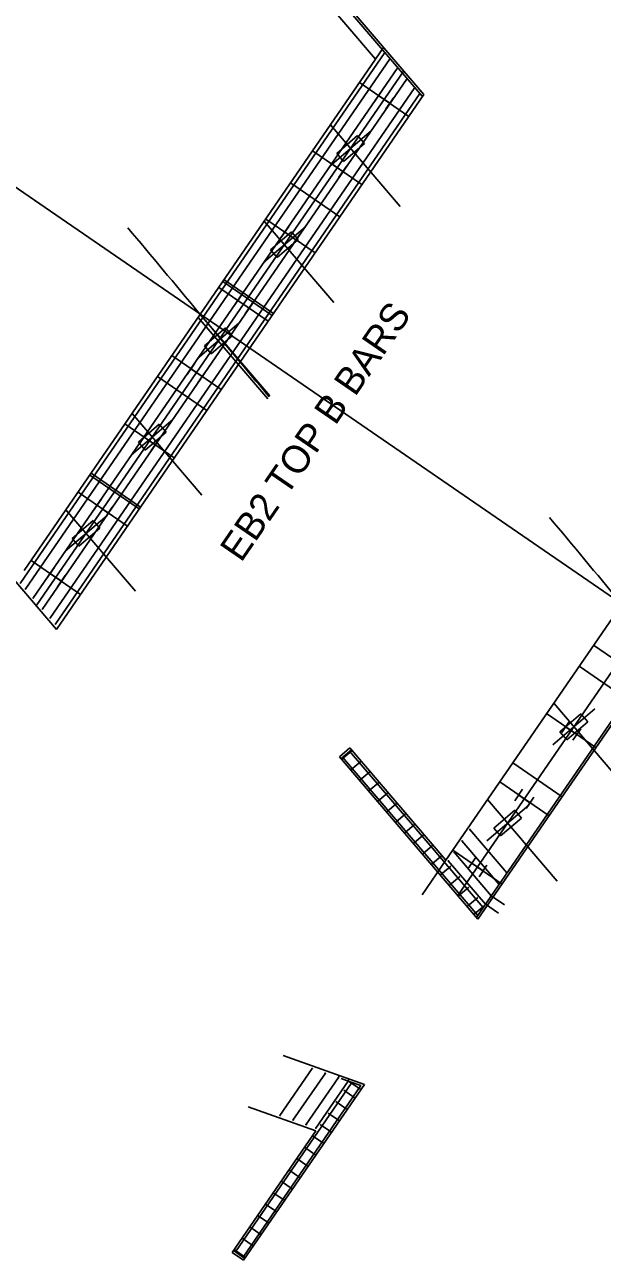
# Model space of a CAD drawing. Extents: x 2378999 to 2381348, y 331302 to 333122.
# Drawn here: x 2379481.1 to 2379522.9, y 331849.1 to 331938.5 of the extents above; entities that cross this region are included whole.
import ezdxf

# ---------------------------------------------------------------- set-up
doc = ezdxf.new("R2010")
doc.units = 0
for name, color, linetype in [('Arrowhead Terminators', 7, 'Continuous'), ('Arrowhead Terminators CELL', 7, 'Continuous'), ('Dimension Lines', 7, 'Continuous'), ('Dimension Lines CELL', 7, 'Continuous'), ('Mis Work Point CELL', 7, 'Continuous'), ('P_SMU_Bent_Cap', 7, 'Continuous'), ('P_SMU_D_Deck_Outline', 7, 'Continuous'), ('P_SMU_Girder_Concrete', 7, 'Continuous'), ('P_SMU_Mis_L_Lines', 7, 'Continuous'), ('P_SMU_Mis_Long_Chord', 7, 'Continuous'), ('P_SMU_Rebar_B_Bar', 7, 'Continuous'), ('P_SMU_Rebar_H_Bar', 7, 'Continuous'), ('P_SMU_Rebar_U_Bar', 7, 'Continuous'), ('P_SMU_Rebar_V_Bar', 7, 'Continuous'), ('Plan Sheet CELL', 7, 'Continuous'), ('Rebar Lines', 7, 'Continuous'), ('Scratch_Level_0', 7, 'Continuous'), ('Sup Concrete Slab Lines', 7, 'Continuous')]:
    doc.layers.add(name, color=color, linetype=linetype)

msp = doc.modelspace()

# ---------------------------------------------------------------- linework, layer by layer
at = {"layer": 'Arrowhead Terminators'}
for p, q in [((2379480.711, 331898.071), (2379507.131, 331936.525)), ((2379481.086, 331897.632), (2379507.505, 331936.086)), ((2379481.646, 331896.976), (2379508.066, 331935.43)), ((2379508.738, 331934.643), (2379482.319, 331896.189)), ((2379509.299, 331933.987), (2379482.879, 331895.533)), ((2379509.673, 331933.549), (2379483.254, 331895.095))]:
    msp.add_line(p, q, dxfattribs=at)
at = {"layer": 'Arrowhead Terminators CELL'}
msp.add_line((2379506.456, 331936.031), (2379507.043, 331936.884), dxfattribs=at)
at = {"layer": 'Dimension Lines'}
for p, q in [((2379511.549, 331878.021), (2379509.836, 331875.529)), ((2379514.841, 331875.454), (2379515.794, 331874.799)), ((2379514.416, 331874.836), (2379515.369, 331874.181)), ((2379503.765, 331862.28), (2379503.82, 331862.437)), ((2379504.472, 331862.03), (2379504.527, 331862.187))]:
    msp.add_line(p, q, dxfattribs=at)
at = {"layer": 'Dimension Lines CELL'}
msp.add_line((2379573.397, 331862.836), (2379390.08, 331988.783), dxfattribs=at)
at = {"layer": 'Mis Work Point CELL'}
for p, q in [((2379481.885, 331896.441), (2379508.5, 331935.179)), ((2379512.42, 331875.462), (2379539.034, 331914.2))]:
    msp.add_line(p, q, dxfattribs=at)
at = {"layer": 'P_SMU_Bent_Cap'}
for p, q in [((2379506.166, 331930.868), (2379503.125, 331928.27)), ((2379501.378, 331923.9), (2379498.337, 331921.301)), ((2379496.591, 331916.931), (2379493.55, 331914.333)), ((2379491.803, 331909.962), (2379488.762, 331907.364)), ((2379487.015, 331902.994), (2379483.974, 331900.396)), ((2379522.338, 331888.984), (2379519.296, 331886.386)), ((2379517.55, 331882.015), (2379514.509, 331879.417))]:
    msp.add_line(p, q, dxfattribs=at)
at = {"layer": 'P_SMU_D_Deck_Outline'}
for p, q in [((2379505.162, 331930.504), (2379503.642, 331929.204)), ((2379505.649, 331929.933), (2379504.129, 331928.634)), ((2379505.649, 331929.933), (2379505.162, 331930.504)), ((2379504.129, 331928.634), (2379503.642, 331929.204)), ((2379500.375, 331923.535), (2379498.854, 331922.236)), ((2379500.862, 331922.965), (2379500.375, 331923.535)), ((2379500.862, 331922.965), (2379499.341, 331921.666)), ((2379499.341, 331921.666), (2379498.854, 331922.236)), ((2379495.587, 331916.566), (2379494.066, 331915.267)), ((2379496.074, 331915.996), (2379495.587, 331916.566)), ((2379496.074, 331915.996), (2379494.553, 331914.697)), ((2379494.553, 331914.697), (2379494.066, 331915.267)), ((2379490.799, 331909.598), (2379489.279, 331908.299)), ((2379491.286, 331909.028), (2379490.799, 331909.598)), ((2379491.286, 331909.028), (2379489.766, 331907.729)), ((2379489.766, 331907.729), (2379489.279, 331908.299)), ((2379486.011, 331902.629), (2379484.491, 331901.33)), ((2379486.499, 331902.059), (2379484.978, 331900.76)), ((2379486.499, 331902.059), (2379486.011, 331902.629)), ((2379484.978, 331900.76), (2379484.491, 331901.33)), ((2379521.334, 331888.619), (2379519.813, 331887.32)), ((2379521.821, 331888.049), (2379520.3, 331886.75)), ((2379521.821, 331888.049), (2379521.334, 331888.619)), ((2379520.3, 331886.75), (2379519.813, 331887.32)), ((2379516.546, 331881.651), (2379515.025, 331880.352)), ((2379517.033, 331881.081), (2379516.546, 331881.651)), ((2379517.033, 331881.081), (2379515.513, 331879.781)), ((2379515.513, 331879.781), (2379515.025, 331880.352))]:
    msp.add_line(p, q, dxfattribs=at)
at = {"layer": 'P_SMU_Girder_Concrete'}
for p, q in [((2379506.396, 331932.985), (2379506.962, 331933.809)), ((2379506.679, 331933.397), (2379507.489, 331932.84)), ((2379507.206, 331932.428), (2379507.772, 331933.252)), ((2379502.998, 331928.039), (2379503.564, 331928.864)), ((2379503.281, 331928.451), (2379504.092, 331927.895)), ((2379503.809, 331927.483), (2379504.375, 331928.307)), ((2379499.6, 331923.094), (2379500.167, 331923.918)), ((2379499.884, 331923.506), (2379500.694, 331922.949)), ((2379500.411, 331922.537), (2379500.977, 331923.361)), ((2379496.203, 331918.149), (2379496.769, 331918.973)), ((2379496.486, 331918.561), (2379497.296, 331918.004)), ((2379497.013, 331917.592), (2379497.58, 331918.416)), ((2379492.805, 331913.203), (2379493.371, 331914.028)), ((2379493.088, 331913.616), (2379493.899, 331913.059)), ((2379493.616, 331912.647), (2379494.182, 331913.471)), ((2379489.408, 331908.258), (2379489.974, 331909.082)), ((2379489.691, 331908.67), (2379490.501, 331908.113)), ((2379490.218, 331907.701), (2379490.784, 331908.526)), ((2379486.01, 331903.313), (2379486.576, 331904.137)), ((2379486.293, 331903.725), (2379487.104, 331903.168)), ((2379486.82, 331902.756), (2379487.387, 331903.58)), ((2379482.612, 331898.367), (2379483.179, 331899.192)), ((2379482.895, 331898.78), (2379483.706, 331898.223)), ((2379483.423, 331897.811), (2379483.989, 331898.635)), ((2379519.942, 331887.28), (2379520.508, 331888.104)), ((2379520.225, 331887.692), (2379521.036, 331887.135)), ((2379520.753, 331886.723), (2379521.319, 331887.547)), ((2379516.544, 331882.334), (2379517.111, 331883.159)), ((2379516.828, 331882.746), (2379517.638, 331882.19)), ((2379517.355, 331881.777), (2379517.921, 331882.602)), ((2379513.147, 331877.389), (2379513.713, 331878.213)), ((2379513.43, 331877.801), (2379514.24, 331877.244)), ((2379513.957, 331876.832), (2379514.524, 331877.656))]:
    msp.add_line(p, q, dxfattribs=at)
at = {"layer": 'P_SMU_Mis_L_Lines'}
for p, q in [((2379508.233, 331925.37), (2379503.188, 331931.274)), ((2379503.445, 331918.401), (2379498.401, 331924.306)), ((2379498.658, 331911.433), (2379493.613, 331917.337)), ((2379493.87, 331904.464), (2379488.825, 331910.369)), ((2379489.082, 331897.496), (2379484.038, 331903.4)), ((2379524.404, 331883.486), (2379519.36, 331889.39)), ((2379519.617, 331876.517), (2379514.572, 331882.422))]:
    msp.add_line(p, q, dxfattribs=at)
at = {"layer": 'P_SMU_Mis_Long_Chord'}
for centre in [(2384926.704, 336457.321), (2384957.239, 336436.342)]:
    msp.add_arc(centre, 7080, 219.8160166, 219.9451668, dxfattribs=at)
at = {"layer": 'P_SMU_Rebar_B_Bar'}
for p, q in [((2379509.957, 331933.473), (2379499.92, 331945.221)), ((2379506.456, 331936.031), (2379499.16, 331944.571)), ((2379506.456, 331936.031), (2379481.014, 331898.999)), ((2379509.957, 331933.473), (2379483.342, 331894.735)), ((2379503.869, 331924.613), (2379500.298, 331927.067)), ((2379499.056, 331917.607), (2379495.484, 331920.061)), ((2379536.991, 331915.053), (2379511.549, 331878.021)), ((2379494.243, 331910.601), (2379490.671, 331913.055)), ((2379540.491, 331912.495), (2379513.877, 331873.757)), ((2379483.342, 331894.735), (2379473.306, 331906.483)), ((2379489.429, 331903.596), (2379485.858, 331906.049)), ((2379524.777, 331889.623), (2379521.206, 331892.077)), ((2379504.6, 331886.154), (2379503.84, 331885.504)), ((2379511.549, 331878.021), (2379504.6, 331886.154)), ((2379513.877, 331873.757), (2379503.84, 331885.504)), ((2379519.964, 331882.617), (2379516.392, 331885.071)), ((2379499.77, 331863.871), (2379505.654, 331861.788)), ((2379505.654, 331861.788), (2379496.904, 331849.053)), ((2379497.23, 331860.173), (2379502.137, 331858.436)), ((2379502.137, 331858.436), (2379496.08, 331849.62)), ((2379496.08, 331849.62), (2379496.904, 331849.053))]:
    msp.add_line(p, q, dxfattribs=at)
at = {"layer": 'P_SMU_Rebar_H_Bar'}
for p, q in [((2379513.862, 331874.03), (2379504.075, 331885.486)), ((2379514.253, 331874.599), (2379504.582, 331885.919)), ((2379514.725, 331875.286), (2379514.253, 331874.599)), ((2379514.334, 331874.717), (2379513.862, 331874.03)), ((2379504.743, 331861.934), (2379496.312, 331849.663)), ((2379503.957, 331862.212), (2379504.743, 331861.934)), ((2379504.608, 331861.982), (2379505.393, 331861.704)), ((2379505.393, 331861.704), (2379496.861, 331849.285))]:
    msp.add_line(p, q, dxfattribs=at)
at = {"layer": 'P_SMU_Rebar_U_Bar'}
for p, q in [((2379515.973, 331877.103), (2379513.283, 331880.251)), ((2379515.407, 331876.278), (2379512.717, 331879.427)), ((2379514.416, 331874.836), (2379511.726, 331877.985)), ((2379514.841, 331875.454), (2379512.151, 331878.603)), ((2379501.879, 331862.947), (2379499.534, 331859.534)), ((2379502.822, 331862.614), (2379500.477, 331859.201)), ((2379503.765, 331862.28), (2379501.42, 331858.867)), ((2379504.472, 331862.03), (2379502.127, 331858.617))]:
    msp.add_line(p, q, dxfattribs=at)
at = {"layer": 'P_SMU_Rebar_V_Bar'}
for centre in [(2379504.145, 331885.436), (2379504.62, 331885.842), (2379505.27, 331885.081), (2379504.795, 331884.675), (2379505.919, 331884.321), (2379505.444, 331883.915), (2379506.569, 331883.561), (2379506.094, 331883.155), (2379506.743, 331882.395), (2379507.219, 331882.801), (2379507.393, 331881.634), (2379507.868, 331882.04), (2379508.042, 331880.874), (2379508.518, 331881.28), (2379508.692, 331880.114), (2379509.167, 331880.52), (2379509.817, 331879.759), (2379513.297, 331880.235), (2379509.342, 331879.353), (2379510.466, 331878.999), (2379512.73, 331879.411), (2379509.991, 331878.593), (2379511.116, 331878.239), (2379511.739, 331877.969), (2379512.164, 331878.587), (2379510.641, 331877.833), (2379511.29, 331877.072), (2379515.96, 331877.118), (2379511.94, 331876.312), (2379515.393, 331876.294), (2379512.589, 331875.552), (2379514.827, 331875.47), (2379513.239, 331874.792), (2379514.402, 331874.852), (2379513.726, 331874.221), (2379501.867, 331862.93), (2379502.81, 331862.597), (2379503.753, 331862.263), (2379504.46, 331862.013), (2379504.819, 331860.905), (2379505.244, 331861.523), (2379504.253, 331860.08), (2379499.546, 331859.551), (2379500.489, 331859.218), (2379503.687, 331859.256), (2379501.431, 331858.884), (2379502.138, 331858.634), (2379503.12, 331858.432), (2379502.039, 331857.962), (2379502.554, 331857.608), (2379501.473, 331857.137), (2379501.988, 331856.783), (2379500.906, 331856.313), (2379501.421, 331855.959), (2379499.774, 331854.665), (2379500.34, 331855.489), (2379500.855, 331855.135), (2379499.208, 331853.841), (2379500.289, 331854.311), (2379498.641, 331853.016), (2379499.723, 331853.487), (2379498.075, 331852.192), (2379499.156, 331852.662), (2379497.509, 331851.368), (2379498.59, 331851.838), (2379496.942, 331850.544), (2379497.458, 331850.19), (2379498.024, 331851.014), (2379496.376, 331849.719), (2379496.891, 331849.365)]:
    msp.add_circle(centre, 0.0208, dxfattribs=at)
at = {"layer": 'Plan Sheet CELL'}
msp.add_line((2379498.804, 331911.646), (2379493.76, 331917.551), dxfattribs=at)
at = {"layer": 'Rebar Lines'}
for p, q in [((2379508.87, 331931.891), (2379505.298, 331934.345)), ((2379505.472, 331926.946), (2379501.901, 331929.4)), ((2379502.075, 331922.001), (2379498.503, 331924.455)), ((2379498.677, 331917.056), (2379495.105, 331919.509)), ((2379495.279, 331912.11), (2379491.708, 331914.564)), ((2379491.882, 331907.165), (2379488.31, 331909.619)), ((2379488.484, 331902.22), (2379484.913, 331904.673)), ((2379485.086, 331897.274), (2379481.515, 331899.728)), ((2379525.814, 331891.132), (2379522.242, 331893.586)), ((2379522.416, 331886.186), (2379518.845, 331888.64)), ((2379519.019, 331881.241), (2379515.447, 331883.695)), ((2379515.621, 331876.296), (2379512.049, 331878.75))]:
    msp.add_line(p, q, dxfattribs=at)
at = {"layer": 'Scratch_Level_0'}
for p, q in [((2379509.83, 331933.365), (2379499.794, 331945.113)), ((2379498.962, 331917.47), (2379495.39, 331919.924)), ((2379540.354, 331912.589), (2379513.739, 331873.851)), ((2379489.335, 331903.458), (2379485.763, 331905.912)), ((2379504.709, 331886.027), (2379503.948, 331885.377)), ((2379504.763, 331885.964), (2379504.002, 331885.314)), ((2379505.412, 331885.203), (2379504.652, 331884.554)), ((2379506.062, 331884.443), (2379505.302, 331883.793)), ((2379506.712, 331883.683), (2379505.951, 331883.033)), ((2379507.361, 331882.922), (2379506.601, 331882.273)), ((2379508.011, 331882.162), (2379507.25, 331881.512)), ((2379508.66, 331881.402), (2379507.9, 331880.752)), ((2379509.31, 331880.641), (2379508.549, 331879.992)), ((2379509.959, 331879.881), (2379509.199, 331879.232)), ((2379510.609, 331879.121), (2379509.849, 331878.471)), ((2379511.259, 331878.361), (2379510.498, 331877.711)), ((2379511.908, 331877.6), (2379511.148, 331876.951)), ((2379512.558, 331876.84), (2379511.797, 331876.19)), ((2379513.207, 331876.08), (2379512.447, 331875.43)), ((2379513.857, 331875.319), (2379513.096, 331874.67)), ((2379514.344, 331874.749), (2379513.584, 331874.1)), ((2379504.574, 331861.983), (2379505.398, 331861.417)), ((2379504.149, 331861.365), (2379504.974, 331860.798)), ((2379503.583, 331860.54), (2379504.407, 331859.974)), ((2379503.017, 331859.716), (2379503.841, 331859.15)), ((2379502.451, 331858.892), (2379503.275, 331858.326)), ((2379501.884, 331858.068), (2379502.709, 331857.502)), ((2379500.752, 331856.419), (2379501.576, 331855.853)), ((2379501.318, 331857.244), (2379502.142, 331856.677)), ((2379500.186, 331855.595), (2379501.01, 331855.029)), ((2379499.619, 331854.771), (2379500.443, 331854.205)), ((2379499.053, 331853.947), (2379499.877, 331853.38)), ((2379498.487, 331853.122), (2379499.311, 331852.556)), ((2379497.92, 331852.298), (2379498.745, 331851.732)), ((2379497.354, 331851.474), (2379498.178, 331850.908)), ((2379496.788, 331850.65), (2379497.612, 331850.084)), ((2379496.174, 331849.757), (2379496.999, 331849.191)), ((2379496.222, 331849.826), (2379497.046, 331849.259))]:
    msp.add_line(p, q, dxfattribs=at)

# ---------------------------------------------------------------- texts
at = {"layer": 'Sup Concrete Slab Lines'}
msp.add_text('EB2 TOP B BARS', height=2, rotation=55.50932, dxfattribs=at).set_placement((2379496.724, 331899.526))

doc.saveas('drawing.dxf')
